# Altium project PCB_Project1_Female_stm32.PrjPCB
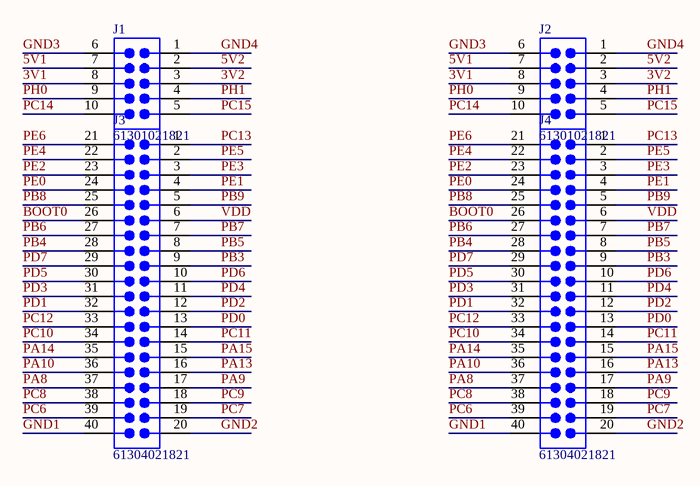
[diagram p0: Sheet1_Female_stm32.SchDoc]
1 sheet, 4 parts. Net scope: global (net labels, ports and power ports of the same name join across sheets).
Board file: PCB1_Female.PcbDoc

## Sheet Sheet1_Female_stm32.SchDoc
size A3

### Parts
J1  61301021821  [61301021821]
J2  61301021821  [61301021821]
J3  61304021821  [61304021821]
J4  61304021821  [61304021821]

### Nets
3V1: J1.8 J2.8
3V2: J1.3 J2.3
5V1: J1.7 J2.7
5V2: J1.2 J2.2
BOOT0: J3.26 J4.26
GND1: J3.40 J4.40
GND2: J3.20 J4.20
GND3: J1.6 J2.6
GND4: J1.1 J2.1
PA8: J3.37 J4.37
PA9: J3.17 J4.17
PA10: J3.36 J4.36
PA13: J3.16 J4.16
PA14: J3.35 J4.35
PA15: J3.15 J4.15
PB3: J3.9 J4.9
PB4: J3.28 J4.28
PB5: J3.8 J4.8
PB6: J3.27 J4.27
PB7: J3.7 J4.7
PB8: J3.25 J4.25
PB9: J3.5 J4.5
PC6: J3.39 J4.39
PC7: J3.19 J4.19
PC8: J3.38 J4.38
PC9: J3.18 J4.18
PC10: J3.34 J4.34
PC11: J3.14 J4.14
PC12: J3.33 J4.33
PC13: J3.1 J4.1
PC14: J1.10 J2.10
PC15: J1.5 J2.5
PD0: J3.13 J4.13
PD1: J3.32 J4.32
PD2: J3.12 J4.12
PD3: J3.31 J4.31
PD4: J3.11 J4.11
PD5: J3.30 J4.30
PD6: J3.10 J4.10
PD7: J3.29 J4.29
PE0: J3.24 J4.24
PE1: J3.4 J4.4
PE2: J3.23 J4.23
PE3: J3.3 J4.3
PE4: J3.22 J4.22
PE5: J3.2 J4.2
PE6: J3.21 J4.21
PH0: J1.9 J2.9
PH1: J1.4 J2.4
VDD: J3.6 J4.6

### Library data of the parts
J1 J2 = JP5x2 2.54MM: 2.54 mm Dual Socket Header, 10p
J3 J4 = JP20x2 2.54MM: 2.54 mm Dual Socket Header, 40p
